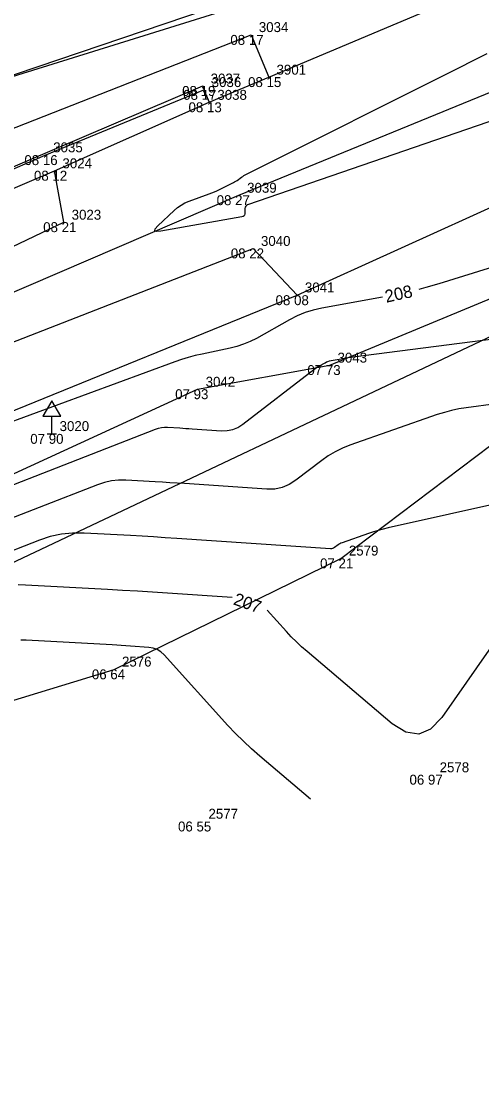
# Model space of a CAD drawing. Extents: x -703403 to -701924, y -1022520 to -1021856.
# Drawn here: x -702392.04 to -702379.06, y -1022322.29 to -1022292.06 of the extents above; entities that cross this region are included whole.
import ezdxf

# ---------------------------------------------------------------- set-up
doc = ezdxf.new("R2010")
doc.units = 0
for name, color, linetype in [('Ex_Contour Labels', 7, 'Continuous'), ('Ex_Major Contours', 7, 'Continuous'), ('Ex_Minor Contours', 7, 'Continuous'), ('Z_body', 7, 'Continuous'), ('Z_body_cisla', 7, 'Continuous'), ('Z_body_vysky_redukovane', 7, 'Continuous'), ('Z_chodnik', 7, 'Continuous'), ('Z_dopravni_znacky', 7, 'Continuous'), ('Z_hrany_paty', 7, 'Continuous'), ('Z_katastr_hranice', 7, 'Continuous'), ('Z_komunikace', 7, 'Continuous'), ('Z_komunikace_osa', 7, 'Continuous'), ('Z_obruba', 7, 'Continuous'), ('Z_rozhranni', 7, 'Continuous')]:
    doc.layers.add(name, color=color, linetype=linetype)

# ---------------------------------------------------------------- blocks, each defined once
blk = doc.blocks.new('POINT_DISPLAY')
blk.add_line((0, 0), (0, 0))
blk = doc.blocks.new('Z527')
for p, q in [((0, 0.93), (-0.25, 0.5)), ((0.25, 0.5), (0, 0.93)), ((-0.25, 0.5), (0.25, 0.5)), ((0, 0), (0, 0.5)), ((-0.13, 0), (0.13, 0))]:
    blk.add_line(p, q)

msp = doc.modelspace()

# ---------------------------------------------------------------- linework, layer by layer
at = {"layer": 'Ex_Major Contours'}
for points in [[(-702393.384, -1022293.943), (-702386.209, -1022291.514)], [(-702377.209, -1022298.508), (-702380.262, -1022299.455), (-702380.633, -1022299.564), (-702380.825, -1022299.614)], [(-702381.852, -1022299.836), (-702383.567, -1022300.144), (-702383.805, -1022300.197), (-702384.036, -1022300.269), (-702384.26, -1022300.36), (-702384.477, -1022300.471), (-702385.408, -1022300.996), (-702385.586, -1022301.087), (-702385.77, -1022301.164), (-702385.959, -1022301.227), (-702386.153, -1022301.274), (-702386.941, -1022301.437), (-702387.137, -1022301.481), (-702387.331, -1022301.532), (-702387.523, -1022301.591), (-702387.713, -1022301.657), (-702395.079, -1022304.369)], [(-702386.094, -1022308.305), (-702387.919, -1022308.182), (-702388.342, -1022308.154), (-702388.764, -1022308.128), (-702389.187, -1022308.103), (-702389.61, -1022308.079), (-702391.922, -1022307.951), (-702392.128, -1022307.95)], [(-702378.504, -1022309.286), (-702380.182, -1022311.682), (-702380.494, -1022312.014), (-702380.831, -1022312.155), (-702381.192, -1022312.104), (-702381.578, -1022311.862), (-702383.979, -1022309.824), (-702384.132, -1022309.69), (-702384.281, -1022309.551), (-702384.424, -1022309.408), (-702384.564, -1022309.259), (-702385.106, -1022308.661)]]:
    msp.add_lwpolyline(points, dxfattribs=at)
at = {"layer": 'Ex_Minor Contours'}
for points in [[(-702378.308, -1022294.707), (-702385.656, -1022297.232), (-702385.687, -1022297.248), (-702385.71, -1022297.27), (-702385.725, -1022297.298), (-702385.731, -1022297.333), (-702385.737, -1022297.484), (-702385.743, -1022297.518), (-702385.758, -1022297.544), (-702385.782, -1022297.563), (-702385.815, -1022297.573), (-702388.108, -1022297.978), (-702388.221, -1022297.987), (-702388.272, -1022297.965), (-702388.26, -1022297.911), (-702388.185, -1022297.825), (-702387.73, -1022297.389), (-702387.635, -1022297.307), (-702387.533, -1022297.236), (-702387.424, -1022297.176), (-702387.308, -1022297.127), (-702386.744, -1022296.922), (-702386.669, -1022296.894), (-702386.595, -1022296.864), (-702386.522, -1022296.832), (-702386.45, -1022296.797), (-702386.091, -1022296.621), (-702386.056, -1022296.603), (-702386.022, -1022296.583), (-702385.988, -1022296.562), (-702385.955, -1022296.541), (-702385.825, -1022296.45), (-702385.792, -1022296.428), (-702385.759, -1022296.407), (-702385.724, -1022296.388), (-702385.689, -1022296.37), (-702379.684, -1022293.361), (-702379.292, -1022293.163), (-702378.901, -1022292.961)], [(-702395.441, -1022306.355), (-702388.251, -1022303.557), (-702388.169, -1022303.53), (-702388.087, -1022303.512), (-702388.002, -1022303.503), (-702387.917, -1022303.504), (-702387.571, -1022303.523), (-702387.484, -1022303.528), (-702387.398, -1022303.533), (-702387.312, -1022303.538), (-702387.225, -1022303.544), (-702386.394, -1022303.6), (-702386.232, -1022303.597), (-702386.077, -1022303.566), (-702385.931, -1022303.506), (-702385.794, -1022303.418), (-702383.786, -1022301.874), (-702383.749, -1022301.847), (-702383.711, -1022301.821), (-702383.672, -1022301.796), (-702383.633, -1022301.773), (-702383.473, -1022301.683), (-702383.432, -1022301.662), (-702383.39, -1022301.645), (-702383.347, -1022301.631), (-702383.302, -1022301.621), (-702382.964, -1022301.561), (-702382.892, -1022301.548), (-702382.821, -1022301.537), (-702382.749, -1022301.526), (-702382.677, -1022301.516), (-702378.362, -1022300.959)], [(-702378.656, -1022302.846), (-702379.494, -1022302.954), (-702379.701, -1022302.987), (-702379.905, -1022303.029), (-702380.107, -1022303.083), (-702380.306, -1022303.147), (-702382.77, -1022304.009), (-702382.982, -1022304.093), (-702383.186, -1022304.193), (-702383.38, -1022304.308), (-702383.566, -1022304.44), (-702384.294, -1022304.999), (-702384.481, -1022305.12), (-702384.681, -1022305.201), (-702384.892, -1022305.244), (-702385.115, -1022305.248), (-702387.441, -1022305.091), (-702387.647, -1022305.078), (-702387.853, -1022305.065), (-702388.06, -1022305.052), (-702388.266, -1022305.04), (-702389.092, -1022304.995), (-702389.297, -1022304.994), (-702389.499, -1022305.015), (-702389.696, -1022305.058), (-702389.891, -1022305.122), (-702394.835, -1022307.046)], [(-702378.229, -1022305.568), (-702381.693, -1022306.34), (-702381.832, -1022306.373), (-702381.97, -1022306.41), (-702382.107, -1022306.452), (-702382.243, -1022306.497), (-702382.994, -1022306.76), (-702383.023, -1022306.771), (-702383.051, -1022306.785), (-702383.078, -1022306.801), (-702383.104, -1022306.819), (-702383.204, -1022306.896), (-702383.23, -1022306.913), (-702383.258, -1022306.924), (-702383.287, -1022306.93), (-702383.318, -1022306.931), (-702387.656, -1022306.638), (-702387.982, -1022306.617), (-702388.309, -1022306.596), (-702388.635, -1022306.577), (-702388.962, -1022306.558), (-702390.268, -1022306.486), (-702390.592, -1022306.485), (-702390.91, -1022306.518), (-702391.223, -1022306.586), (-702391.531, -1022306.687), (-702394.228, -1022307.737)], [(-702383.88, -1022313.991), (-702385.313, -1022312.776), (-702385.548, -1022312.57), (-702385.776, -1022312.357), (-702385.997, -1022312.136), (-702386.21, -1022311.908), (-702388.013, -1022309.918), (-702388.105, -1022309.833), (-702388.208, -1022309.77), (-702388.321, -1022309.728), (-702388.445, -1022309.709), (-702388.961, -1022309.674), (-702389.091, -1022309.665), (-702389.22, -1022309.657), (-702389.349, -1022309.649), (-702389.478, -1022309.642), (-702391.904, -1022309.508), (-702392.052, -1022309.51)]]:
    msp.add_lwpolyline(points, dxfattribs=at)
at = {"layer": 'Z_chodnik'}
for p, q in [((-702398.71, -1022297.6), (-702385.56, -1022292.44)), ((-702385.56, -1022292.44), (-702385.06, -1022293.63))]:
    msp.add_line(p, q, dxfattribs=at)
at = {"layer": 'Z_hrany_paty'}
for p, q in [((-702396.21, -1022294.84), (-702384.72, -1022291.25)), ((-702383.34, -1022301.75), (-702378.15, -1022299.6)), ((-702387.07, -1022302.43), (-702383.34, -1022301.75)), ((-702395.49, -1022306.3), (-702387.07, -1022302.43)), ((-702383.03, -1022307.2), (-702378.27, -1022303.61)), ((-702389.42, -1022310.33), (-702383.03, -1022307.2)), ((-702401.11, -1022313.92), (-702389.42, -1022310.33))]:
    msp.add_line(p, q, dxfattribs=at)
at = {"layer": 'Z_katastr_hranice'}
msp.add_line((-702423.94, -1022322.29), (-702361.39, -1022292.7), dxfattribs=at)
at = {"layer": 'Z_komunikace'}
for p, q in [((-702385.06, -1022293.63), (-702376.42, -1022289.99)), ((-702386.74, -1022294.34), (-702385.06, -1022293.63)), ((-702391.37, -1022295.83), (-702386.89, -1022293.99)), ((-702386.89, -1022293.99), (-702386.74, -1022294.34)), ((-702384.26, -1022299.78), (-702373.93, -1022295.09)), ((-702398.37, -1022298.86), (-702391.37, -1022295.83)), ((-702396.09, -1022304.59), (-702384.26, -1022299.78))]:
    msp.add_line(p, q, dxfattribs=at)
at = {"layer": 'Z_komunikace_osa'}
for p, q in [((-702385.9, -1022296.96), (-702375.2, -1022292.57)), ((-702397.14, -1022301.77), (-702385.9, -1022296.96))]:
    msp.add_line(p, q, dxfattribs=at)
at = {"layer": 'Z_obruba'}
for p, q in [((-702398.38, -1022298.76), (-702386.92, -1022293.88)), ((-702386.92, -1022293.88), (-702386.89, -1022293.99))]:
    msp.add_line(p, q, dxfattribs=at)
at = {"layer": 'Z_rozhranni'}
for p, q in [((-702391.1, -1022296.27), (-702386.74, -1022294.34)), ((-702395.97, -1022298.34), (-702391.1, -1022296.27)), ((-702390.84, -1022297.72), (-702391.1, -1022296.27)), ((-702394.85, -1022299.62), (-702390.84, -1022297.72)), ((-702396.7, -1022302.82), (-702385.5, -1022298.46)), ((-702385.5, -1022298.46), (-702384.26, -1022299.78))]:
    msp.add_line(p, q, dxfattribs=at)

# ---------------------------------------------------------------- block references
at = {"layer": 'Z_body'}
for p in [(-702385.56, -1022292.44), (-702385.06, -1022293.63), (-702386.92, -1022293.88), (-702386.89, -1022293.99), (-702386.74, -1022294.34), (-702391.37, -1022295.83), (-702391.1, -1022296.27), (-702385.9, -1022296.96), (-702390.84, -1022297.72), (-702385.5, -1022298.46), (-702384.26, -1022299.78), (-702383.34, -1022301.75), (-702387.07, -1022302.43), (-702391.18, -1022303.69), (-702383.03, -1022307.2), (-702389.42, -1022310.33), (-702380.46, -1022313.3), (-702386.99, -1022314.62)]:
    msp.add_blockref('POINT_DISPLAY', p, dxfattribs=at)
at = {"layer": 'Z_dopravni_znacky'}
msp.add_blockref('Z527', (-702391.18, -1022303.69), dxfattribs=at)

# ---------------------------------------------------------------- texts
at = {"layer": 'Ex_Contour Labels'}
for s, rotation, p in [('208', 12.2491, (-702381.743, -1022299.992)), ('207', 340.3622, (-702386.083, -1022308.491))]:
    msp.add_text(s, height=0.35, rotation=rotation, dxfattribs=at).set_placement(p)
at = {"layer": 'Z_body_cisla'}
for s, p in [('3034', (-702385.34, -1022292.36)), ('3901', (-702384.84, -1022293.56)), ('3037', (-702386.7, -1022293.81)), ('3036', (-702386.67, -1022293.91)), ('3038', (-702386.51, -1022294.27)), ('3035', (-702391.14, -1022295.75)), ('3024', (-702390.88, -1022296.2)), ('3039', (-702385.67, -1022296.89)), ('3023', (-702390.62, -1022297.65)), ('3040', (-702385.28, -1022298.39)), ('3041', (-702384.04, -1022299.7)), ('3043', (-702383.12, -1022301.68)), ('3042', (-702386.84, -1022302.36)), ('3020', (-702390.96, -1022303.61)), ('2579', (-702382.8, -1022307.12)), ('2576', (-702389.2, -1022310.25)), ('2578', (-702380.24, -1022313.23)), ('2577', (-702386.76, -1022314.54))]:
    msp.add_text(s, height=0.28, dxfattribs=at).set_placement(p)
at = {"layer": 'Z_body_vysky_redukovane'}
for s, p in [('08 17', (-702386.143, -1022292.72)), ('08 15', (-702385.643, -1022293.91)), ('08 19', (-702387.503, -1022294.16)), ('08 17', (-702387.473, -1022294.27)), ('08 13', (-702387.323, -1022294.62)), ('08 16', (-702391.953, -1022296.11)), ('08 12', (-702391.683, -1022296.55)), ('08 27', (-702386.53, -1022297.24)), ('08 21', (-702391.423, -1022298)), ('08 22', (-702386.13, -1022298.74)), ('08 08', (-702384.867, -1022300.06)), ('07 73', (-702383.97, -1022302.03)), ('07 93', (-702387.7, -1022302.71)), ('07 90', (-702391.787, -1022303.97)), ('07 21', (-702383.613, -1022307.48)), ('06 64', (-702390.05, -1022310.61)), ('06 97', (-702381.09, -1022313.58)), ('06 55', (-702387.62, -1022314.9))]:
    msp.add_text(s, height=0.28, dxfattribs=at).set_placement(p)

doc.saveas('drawing.dxf')
